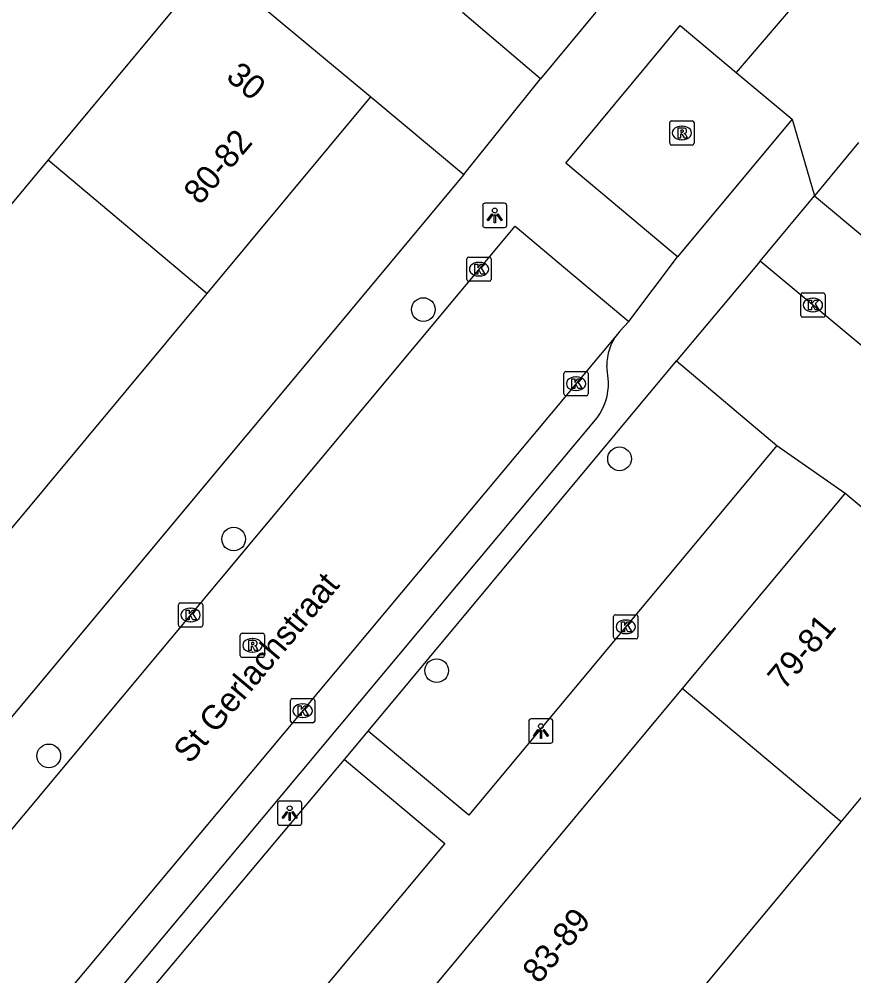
# Model space of a CAD drawing. Extents: x 162532 to 163264, y 381233 to 382042.
# Drawn here: x 162920.22 to 162954.65, y 381584.03 to 381623.51 of the extents above; entities that cross this region are included whole.
import ezdxf

# ---------------------------------------------------------------- set-up
doc = ezdxf.new("R2010")
doc.units = 0
for name, color, linetype in [('IMGEO_Boom', 7, 'Continuous'), ('IMGEO_Kolk', 7, 'Continuous'), ('IMGEO_Lichtpunt', 7, 'Continuous'), ('IMGEO_Openbare_ruimte_label', 7, 'Continuous'), ('IMGEO_Pand', 7, 'Continuous'), ('IMGEO_Pand_nummerreeks', 7, 'Continuous'), ('IMGEO_Rijbaan_lokaal_open', 7, 'Continuous'), ('IMGEO_Rioolput', 7, 'Continuous'), ('IMGEO_Voetpad_open', 7, 'Continuous')]:
    doc.layers.add(name, color=color, linetype=linetype)

msp = doc.modelspace()

# ---------------------------------------------------------------- linework, layer by layer
at = {"layer": 'IMGEO_Boom'}
for centre in [(162936.894, 381611.526), (162944.987, 381605.367), (162929.071, 381602.057), (162937.442, 381596.626), (162921.443, 381593.11)]:
    msp.add_circle(centre, 0.489, dxfattribs=at)
at = {"layer": 'IMGEO_Kolk'}
for p, q in [((162938.69, 381612.768), (162938.69, 381613.62)), ((162938.765, 381613.694), (162939.617, 381613.694)), ((162939.178, 381613.474), (162939.203, 381613.474)), ((162939.691, 381613.62), (162939.691, 381612.768)), ((162939.617, 381612.694), (162938.765, 381612.694)), ((162939.201, 381612.914), (162939.176, 381612.914)), ((162952.536, 381612.212), (162953.388, 381612.212)), ((162952.461, 381611.286), (162952.461, 381612.138)), ((162952.949, 381611.992), (162952.974, 381611.992)), ((162953.462, 381612.138), (162953.462, 381611.286)), ((162952.972, 381611.432), (162952.947, 381611.432)), ((162953.388, 381611.212), (162952.536, 381611.212)), ((162942.692, 381608.043), (162942.692, 381608.895)), ((162942.767, 381608.969), (162943.619, 381608.969)), ((162943.18, 381608.749), (162943.205, 381608.749)), ((162943.693, 381608.895), (162943.693, 381608.043)), ((162943.619, 381607.969), (162942.767, 381607.969)), ((162943.203, 381608.189), (162943.178, 381608.189)), ((162926.792, 381598.497), (162926.792, 381599.349)), ((162926.867, 381599.423), (162927.719, 381599.423)), ((162927.28, 381599.203), (162927.305, 381599.203)), ((162927.793, 381599.349), (162927.793, 381598.497)), ((162944.741, 381598.009), (162944.741, 381598.861)), ((162944.816, 381598.935), (162945.668, 381598.935)), ((162945.742, 381598.861), (162945.742, 381598.009)), ((162927.719, 381598.423), (162926.867, 381598.423)), ((162927.303, 381598.643), (162927.278, 381598.643)), ((162945.229, 381598.715), (162945.254, 381598.715)), ((162945.252, 381598.155), (162945.227, 381598.155)), ((162945.668, 381597.935), (162944.816, 381597.935)), ((162931.414, 381594.547), (162931.414, 381595.399)), ((162931.489, 381595.473), (162932.341, 381595.473)), ((162931.902, 381595.253), (162931.927, 381595.253)), ((162932.415, 381595.399), (162932.415, 381594.547)), ((162932.341, 381594.473), (162931.489, 381594.473)), ((162931.925, 381594.693), (162931.9, 381594.693))]:
    msp.add_line(p, q, dxfattribs=at)
for points in [[(162938.69, 381612.768), (162938.69, 381613.62)], [(162938.765, 381613.694), (162939.617, 381613.694)], [(162939.011, 381613.394), (162939.134, 381613.394), (162939.134, 381613.243), (162939.264, 381613.394), (162939.428, 381613.394), (162939.282, 381613.243), (162939.435, 381612.994), (162939.283, 381612.994), (162939.198, 381613.158), (162939.134, 381613.091), (162939.134, 381612.994), (162939.011, 381612.994), (162939.011, 381613.394)], [(162939.691, 381613.62), (162939.691, 381612.768)], [(162939.617, 381612.694), (162938.765, 381612.694)], [(162952.536, 381612.212), (162953.388, 381612.212)], [(162952.461, 381611.286), (162952.461, 381612.138)], [(162952.782, 381611.912), (162952.905, 381611.912), (162952.905, 381611.761), (162953.035, 381611.912), (162953.199, 381611.912), (162953.053, 381611.761), (162953.206, 381611.512), (162953.054, 381611.512), (162952.969, 381611.676), (162952.905, 381611.609), (162952.905, 381611.512), (162952.782, 381611.512), (162952.782, 381611.912)], [(162953.462, 381612.138), (162953.462, 381611.286)], [(162953.388, 381611.212), (162952.536, 381611.212)], [(162942.692, 381608.043), (162942.692, 381608.895)], [(162942.767, 381608.969), (162943.619, 381608.969)], [(162943.013, 381608.669), (162943.136, 381608.669), (162943.136, 381608.518), (162943.266, 381608.669), (162943.43, 381608.669), (162943.284, 381608.518), (162943.437, 381608.269), (162943.285, 381608.269), (162943.2, 381608.433), (162943.136, 381608.366), (162943.136, 381608.269), (162943.013, 381608.269), (162943.013, 381608.669)], [(162943.693, 381608.895), (162943.693, 381608.043)], [(162943.619, 381607.969), (162942.767, 381607.969)], [(162926.792, 381598.497), (162926.792, 381599.349)], [(162926.867, 381599.423), (162927.719, 381599.423)], [(162927.793, 381599.349), (162927.793, 381598.497)], [(162927.113, 381599.123), (162927.236, 381599.123), (162927.236, 381598.972), (162927.366, 381599.123), (162927.53, 381599.123), (162927.384, 381598.972), (162927.537, 381598.723), (162927.385, 381598.723), (162927.3, 381598.887), (162927.236, 381598.82), (162927.236, 381598.723), (162927.113, 381598.723), (162927.113, 381599.123)], [(162944.741, 381598.009), (162944.741, 381598.861)], [(162944.816, 381598.935), (162945.668, 381598.935)], [(162945.742, 381598.861), (162945.742, 381598.009)], [(162927.719, 381598.423), (162926.867, 381598.423)], [(162945.062, 381598.635), (162945.185, 381598.635), (162945.185, 381598.484), (162945.315, 381598.635), (162945.479, 381598.635), (162945.333, 381598.484), (162945.486, 381598.235), (162945.334, 381598.235), (162945.249, 381598.399), (162945.185, 381598.332), (162945.185, 381598.235), (162945.062, 381598.235), (162945.062, 381598.635)], [(162945.668, 381597.935), (162944.816, 381597.935)], [(162931.414, 381594.547), (162931.414, 381595.399)], [(162931.489, 381595.473), (162932.341, 381595.473)], [(162932.415, 381595.399), (162932.415, 381594.547)], [(162931.735, 381595.173), (162931.858, 381595.173), (162931.858, 381595.022), (162931.988, 381595.173), (162932.152, 381595.173), (162932.006, 381595.022), (162932.159, 381594.773), (162932.007, 381594.773), (162931.922, 381594.937), (162931.858, 381594.87), (162931.858, 381594.773), (162931.735, 381594.773), (162931.735, 381595.173)], [(162932.341, 381594.473), (162931.489, 381594.473)]]:
    msp.add_lwpolyline(points, dxfattribs=at)
for centre, start, end in [((162938.767, 381613.618), 91.552, 178.448), ((162938.767, 381613.618), 91.552, 178.448), ((162939.615, 381613.618), 1.552, 88.448), ((162939.615, 381613.618), 1.552, 88.448), ((162938.767, 381612.77), 181.552, 268.448), ((162938.767, 381612.77), 181.552, 268.448), ((162939.615, 381612.77), 271.552, 358.448), ((162939.615, 381612.77), 271.552, 358.448), ((162952.538, 381612.136), 91.552, 178.448), ((162952.538, 381612.136), 91.552, 178.448), ((162953.386, 381612.136), 1.552, 88.448), ((162953.386, 381612.136), 1.552, 88.448), ((162952.538, 381611.288), 181.552, 268.448), ((162952.538, 381611.288), 181.552, 268.448), ((162953.386, 381611.288), 271.552, 358.448), ((162953.386, 381611.288), 271.552, 358.448), ((162942.769, 381608.893), 91.552, 178.448), ((162942.769, 381608.893), 91.552, 178.448), ((162943.617, 381608.893), 1.552, 88.448), ((162943.617, 381608.893), 1.552, 88.448), ((162942.769, 381608.045), 181.552, 268.448), ((162942.769, 381608.045), 181.552, 268.448), ((162943.617, 381608.045), 271.552, 358.448), ((162943.617, 381608.045), 271.552, 358.448), ((162926.869, 381599.347), 91.552, 178.448), ((162926.869, 381599.347), 91.552, 178.448), ((162927.717, 381599.347), 1.552, 88.448), ((162927.717, 381599.347), 1.552, 88.448), ((162944.818, 381598.859), 91.552, 178.448), ((162944.818, 381598.859), 91.552, 178.448), ((162945.666, 381598.859), 1.552, 88.448), ((162945.666, 381598.859), 1.552, 88.448), ((162926.869, 381598.499), 181.552, 268.448), ((162926.869, 381598.499), 181.552, 268.448), ((162927.717, 381598.499), 271.552, 358.448), ((162927.717, 381598.499), 271.552, 358.448), ((162944.818, 381598.011), 181.552, 268.448), ((162944.818, 381598.011), 181.552, 268.448), ((162945.666, 381598.011), 271.552, 358.448), ((162945.666, 381598.011), 271.552, 358.448), ((162931.491, 381595.397), 91.552, 178.448), ((162931.491, 381595.397), 91.552, 178.448), ((162932.339, 381595.397), 1.552, 88.448), ((162932.339, 381595.397), 1.552, 88.448), ((162931.491, 381594.549), 181.552, 268.448), ((162931.491, 381594.549), 181.552, 268.448), ((162932.339, 381594.549), 271.552, 358.448), ((162932.339, 381594.549), 271.552, 358.448)]:
    msp.add_arc(centre, 0.0765, start, end, dxfattribs=at)
for centre, major_axis, ratio, start_param, end_param in [((162939.177, 381613.194), (-0.387, 0.002), 0.722429, 4.712389, 7.853982), ((162939.202, 381613.194), (-0.39, 0.002), 0.717154, 1.570796, 4.712389), ((162952.948, 381611.712), (-0.387, 0.002), 0.722429, 4.712389, 7.853982), ((162952.973, 381611.712), (-0.39, 0.002), 0.717154, 1.570796, 4.712389), ((162943.179, 381608.469), (-0.387, 0.002), 0.722429, 4.712389, 7.853982), ((162943.204, 381608.469), (-0.39, 0.002), 0.717154, 1.570796, 4.712389), ((162927.279, 381598.923), (-0.387, 0.002), 0.722429, 4.712389, 7.853982), ((162927.304, 381598.923), (-0.39, 0.002), 0.717154, 1.570796, 4.712389), ((162945.228, 381598.435), (-0.387, 0.002), 0.722429, 4.712389, 7.853982), ((162945.253, 381598.435), (-0.39, 0.002), 0.717154, 1.570796, 4.712389), ((162931.901, 381594.973), (-0.387, 0.002), 0.722429, 4.712389, 7.853982), ((162931.926, 381594.973), (-0.39, 0.002), 0.717154, 1.570796, 4.712389)]:
    msp.add_ellipse(centre, major_axis=major_axis, ratio=ratio, start_param=start_param, end_param=end_param, dxfattribs=at)
at = {"layer": 'IMGEO_Lichtpunt'}
for p, q in [((162939.34, 381615.818), (162939.34, 381615.011)), ((162939.34, 381615.818), (162939.34, 381615.011)), ((162940.242, 381615.913), (162939.434, 381615.913)), ((162940.242, 381615.913), (162939.434, 381615.913)), ((162940.336, 381615.011), (162940.336, 381615.818)), ((162940.336, 381615.011), (162940.336, 381615.818)), ((162939.434, 381614.917), (162940.242, 381614.917)), ((162939.434, 381614.917), (162940.242, 381614.917)), ((162941.243, 381594.538), (162941.243, 381593.731)), ((162941.243, 381594.538), (162941.243, 381593.731)), ((162942.145, 381594.633), (162941.337, 381594.633)), ((162942.145, 381594.633), (162941.337, 381594.633)), ((162942.239, 381593.731), (162942.239, 381594.538)), ((162942.239, 381593.731), (162942.239, 381594.538)), ((162941.337, 381593.637), (162942.145, 381593.637)), ((162941.337, 381593.637), (162942.145, 381593.637)), ((162930.883, 381591.151), (162930.883, 381590.344)), ((162930.883, 381591.151), (162930.883, 381590.344)), ((162931.785, 381591.246), (162930.977, 381591.246)), ((162931.785, 381591.246), (162930.977, 381591.246)), ((162931.879, 381590.344), (162931.879, 381591.151)), ((162931.879, 381590.344), (162931.879, 381591.151)), ((162930.977, 381590.25), (162931.785, 381590.25)), ((162930.977, 381590.25), (162931.785, 381590.25))]:
    msp.add_line(p, q, dxfattribs=at)
for points in [[(162939.714, 381615.482), (162939.753, 381615.454), (162939.565, 381615.192), (162939.527, 381615.219), (162939.714, 381615.482)], [(162939.816, 381615.434), (162939.863, 381615.434), (162939.863, 381615.112), (162939.816, 381615.112), (162939.816, 381615.434)], [(162939.926, 381615.454), (162939.964, 381615.481), (162940.151, 381615.219), (162940.112, 381615.191), (162939.926, 381615.454)], [(162941.617, 381594.202), (162941.656, 381594.174), (162941.468, 381593.912), (162941.43, 381593.939), (162941.617, 381594.202)], [(162941.719, 381594.154), (162941.766, 381594.154), (162941.766, 381593.832), (162941.719, 381593.832), (162941.719, 381594.154)], [(162941.829, 381594.174), (162941.867, 381594.201), (162942.054, 381593.939), (162942.015, 381593.911), (162941.829, 381594.174)], [(162931.257, 381590.815), (162931.296, 381590.787), (162931.108, 381590.525), (162931.07, 381590.552), (162931.257, 381590.815)], [(162931.359, 381590.767), (162931.406, 381590.767), (162931.406, 381590.445), (162931.359, 381590.445), (162931.359, 381590.767)], [(162931.469, 381590.787), (162931.507, 381590.814), (162931.694, 381590.552), (162931.655, 381590.524), (162931.469, 381590.787)]]:
    msp.add_lwpolyline(points, dxfattribs=at)
for centre in [(162939.839, 381615.616), (162941.742, 381594.336), (162931.382, 381590.949)]:
    msp.add_circle(centre, 0.0994, dxfattribs=at)
for centre, start, end in [((162939.434, 381615.818), 90, 180), ((162939.434, 381615.818), 90, 180), ((162940.242, 381615.818), 0, 90), ((162940.242, 381615.818), 0, 90), ((162939.434, 381615.011), 180, 270), ((162939.434, 381615.011), 180, 270), ((162940.242, 381615.011), 270, 0), ((162940.242, 381615.011), 270, 360), ((162941.337, 381594.538), 90, 180), ((162941.337, 381594.538), 90, 180), ((162942.145, 381594.538), 0, 90), ((162942.145, 381594.538), 0, 90), ((162941.337, 381593.731), 180, 270), ((162941.337, 381593.731), 180, 270), ((162942.145, 381593.731), 270, 0), ((162942.145, 381593.731), 270, 360), ((162930.977, 381591.151), 90, 180), ((162930.977, 381591.151), 90, 180), ((162931.785, 381591.151), 0, 90), ((162931.785, 381591.151), 0, 90), ((162930.977, 381590.344), 180, 270), ((162930.977, 381590.344), 180, 270), ((162931.785, 381590.344), 270, 0), ((162931.785, 381590.344), 270, 360)]:
    msp.add_arc(centre, 0.0946, start, end, dxfattribs=at)
at = {"layer": 'IMGEO_Pand'}
for points in [[(162928.147, 381625.792), (162921.421, 381617.708)], [(162928.147, 381625.792), (162934.732, 381620.307)], [(162927.977, 381612.195), (162934.732, 381620.307)], [(162921.421, 381617.708), (162908.05, 381601.637)], [(162921.421, 381617.708), (162927.977, 381612.195)], [(162914.597, 381596.129), (162927.977, 381612.195)], [(162954.285, 381603.956), (162947.564, 381595.884)], [(162954.285, 381603.956), (162960.864, 381598.479)], [(162954.121, 381590.381), (162960.864, 381598.479)], [(162947.564, 381595.884), (162934.171, 381579.799)], [(162954.121, 381590.381), (162947.564, 381595.884)], [(162940.729, 381574.297), (162954.121, 381590.381)]]:
    msp.add_lwpolyline(points, dxfattribs=at)
at = {"layer": 'IMGEO_Rijbaan_lokaal_open'}
for points in [[(162941.732, 381621.049), (162938.502, 381623.781)], [(162944.009, 381623.798), (162941.732, 381621.049)], [(162947.38, 381613.702), (162945.072, 381615.639), (162942.764, 381617.575), (162947.489, 381623.243), (162949.795, 381621.313)], [(162949.795, 381621.313), (162952.1, 381619.384)], [(162952.1, 381619.384), (162947.38, 381613.702)], [(162950.782, 381613.529), (162953.023, 381616.223)], [(162953.023, 381616.223), (162959.497, 381610.819)], [(162918.918, 381579.401), (162916.611, 381581.371), (162914.303, 381583.342), (162940.674, 381614.971), (162943.022, 381613.001), (162945.369, 381611.032)], [(162961.614, 381604.504), (162957.551, 381607.889), (162950.782, 381613.529)], [(162945.369, 381611.032), (162944.997, 381610.63), (162944.899, 381610.512)], [(162944.899, 381610.512), (162919.507, 381580.127)]]:
    msp.add_lwpolyline(points, dxfattribs=at)
at = {"layer": 'IMGEO_Rioolput'}
for p, q in [((162947.131, 381619.314), (162947.983, 381619.314)), ((162947.056, 381618.388), (162947.056, 381619.24)), ((162947.544, 381619.094), (162947.569, 381619.094)), ((162948.057, 381619.24), (162948.057, 381618.388)), ((162947.567, 381618.534), (162947.542, 381618.534)), ((162947.983, 381618.314), (162947.131, 381618.314)), ((162929.343, 381597.245), (162929.343, 381598.097)), ((162929.418, 381598.171), (162930.27, 381598.171)), ((162930.344, 381598.097), (162930.344, 381597.245)), ((162929.831, 381597.951), (162929.856, 381597.951)), ((162929.854, 381597.391), (162929.829, 381597.391)), ((162930.27, 381597.171), (162929.418, 381597.171))]:
    msp.add_line(p, q, dxfattribs=at)
for points in [[(162947.131, 381619.314), (162947.983, 381619.314)], [(162947.056, 381618.388), (162947.056, 381619.24)], [(162947.645, 381619.012), (162947.393, 381619.014), (162947.393, 381618.614)], [(162947.571, 381618.933), (162947.517, 381618.933), (162947.517, 381618.852)], [(162948.057, 381619.24), (162948.057, 381618.388)], [(162947.393, 381618.614), (162947.517, 381618.614), (162947.517, 381618.776), (162947.528, 381618.776)], [(162947.517, 381618.852), (162947.569, 381618.852)], [(162947.575, 381618.747), (162947.646, 381618.614), (162947.786, 381618.614), (162947.721, 381618.74)], [(162947.983, 381618.314), (162947.131, 381618.314)], [(162929.343, 381597.245), (162929.343, 381598.097)], [(162929.418, 381598.171), (162930.27, 381598.171)], [(162930.344, 381598.097), (162930.344, 381597.245)], [(162929.932, 381597.869), (162929.68, 381597.871), (162929.68, 381597.471)], [(162929.68, 381597.471), (162929.804, 381597.471), (162929.804, 381597.633), (162929.815, 381597.633)], [(162929.858, 381597.79), (162929.804, 381597.79), (162929.804, 381597.709)], [(162929.804, 381597.709), (162929.856, 381597.709)], [(162929.862, 381597.604), (162929.933, 381597.471), (162930.073, 381597.471), (162930.008, 381597.597)], [(162930.27, 381597.171), (162929.418, 381597.171)]]:
    msp.add_lwpolyline(points, dxfattribs=at)
for centre, radius, start, end in [((162947.133, 381619.238), 0.0765, 91.552, 178.448), ((162947.133, 381619.238), 0.0765, 91.552, 178.448), ((162947.981, 381619.238), 0.0765, 1.552, 88.448), ((162947.981, 381619.238), 0.0765, 1.552, 88.448), ((162947.577, 381618.837), 0.0964, 77.0061, 93.1865), ((162947.591, 381618.894), 0.0378, 276.6634, 79.6772), ((162947.644, 381618.902), 0.109, 350.3612, 89.416), ((162947.527, 381618.723), 0.0533, 26.0293, 88.6989), ((162947.553, 381619.041), 0.19, 274.7715, 282.9687), ((162947.642, 381618.902), 0.112, 277.5842, 350.9817), ((162947.626, 381618.687), 0.108, 29.5134, 73.7905), ((162947.133, 381618.39), 0.0765, 181.552, 268.448), ((162947.133, 381618.39), 0.0765, 181.552, 268.448), ((162947.981, 381618.39), 0.0765, 271.552, 358.448), ((162947.981, 381618.39), 0.0765, 271.552, 358.448), ((162929.42, 381598.095), 0.0765, 91.552, 178.448), ((162929.42, 381598.095), 0.0765, 91.552, 178.448), ((162930.268, 381598.095), 0.0765, 1.552, 88.448), ((162930.268, 381598.095), 0.0765, 1.552, 88.448), ((162929.814, 381597.58), 0.0533, 26.0293, 88.6989), ((162929.84, 381597.898), 0.19, 274.7715, 282.9687), ((162929.864, 381597.694), 0.0964, 77.0061, 93.1865), ((162929.878, 381597.751), 0.0378, 276.6634, 79.6772), ((162929.931, 381597.759), 0.109, 350.3612, 89.416), ((162929.929, 381597.759), 0.112, 277.5842, 350.9817), ((162929.913, 381597.544), 0.108, 29.5134, 73.7905), ((162929.42, 381597.247), 0.0765, 181.552, 268.448), ((162929.42, 381597.247), 0.0765, 181.552, 268.448), ((162930.268, 381597.247), 0.0765, 271.552, 358.448), ((162930.268, 381597.247), 0.0765, 271.552, 358.448)]:
    msp.add_arc(centre, radius, start, end, dxfattribs=at)
for centre, major_axis, ratio, start_param, end_param in [((162947.543, 381618.814), (-0.387, 0.002), 0.722429, 4.712389, 7.853982), ((162947.568, 381618.814), (-0.39, 0.002), 0.717154, 1.570796, 4.712389), ((162929.83, 381597.671), (-0.387, 0.002), 0.722429, 4.712389, 7.853982), ((162929.855, 381597.671), (-0.39, 0.002), 0.717154, 1.570796, 4.712389)]:
    msp.add_ellipse(centre, major_axis=major_axis, ratio=ratio, start_param=start_param, end_param=end_param, dxfattribs=at)
at = {"layer": 'IMGEO_Voetpad_open'}
for points in [[(162954.316, 381626.612), (162949.795, 381621.313)], [(162938.568, 381617.099), (162941.732, 381621.049)], [(162934.732, 381620.307), (162938.568, 381617.099)], [(162952.1, 381619.384), (162953.023, 381616.223)], [(162954.837, 381618.426), (162953.023, 381616.223)], [(162938.568, 381617.099), (162911.768, 381584.95)], [(162945.369, 381611.032), (162947.38, 381613.702)], [(162950.782, 381613.529), (162947.33, 381609.407)], [(162934.619, 381594.127), (162947.33, 381609.407)], [(162944.53, 381608.551), (162944.463, 381609.205)], [(162947.33, 381609.407), (162951.476, 381605.922)], [(162922.876, 381581.693), (162944.063, 381607.062)], [(162951.476, 381605.922), (162938.764, 381590.661), (162934.619, 381594.127)], [(162951.476, 381605.922), (162954.285, 381603.956)], [(162933.64, 381592.954), (162934.619, 381594.127)], [(162920.788, 381577.63), (162933.64, 381592.954)], [(162933.64, 381592.954), (162937.778, 381589.495), (162924.941, 381574.118)]]:
    msp.add_lwpolyline(points, dxfattribs=at)
for centre, radius, start, end in [((162946.531, 381609.241), 2.068, 142.0945, 181.0093), ((162942.135, 381608.484), 2.396, 323.5804, 1.5932)]:
    msp.add_arc(centre, radius, start, end, dxfattribs=at)

# ---------------------------------------------------------------- texts
at = {"layer": 'IMGEO_Openbare_ruimte_label'}
msp.add_text('St Gerlachstraat', height=1, rotation=49.989, dxfattribs=at).set_placement((162927.269, 381592.74))
at = {"layer": 'IMGEO_Pand_nummerreeks'}
for s, rotation, p in [('30', 320.2073, (162928.707, 381621.056)), ('80-82', 49.6701, (162927.683, 381615.806)), ('79-81', 50.1022, (162951.771, 381595.782)), ('83-89', 50.1479, (162941.661, 381583.665))]:
    msp.add_text(s, height=1, rotation=rotation, dxfattribs=at).set_placement(p)

doc.saveas('drawing.dxf')
